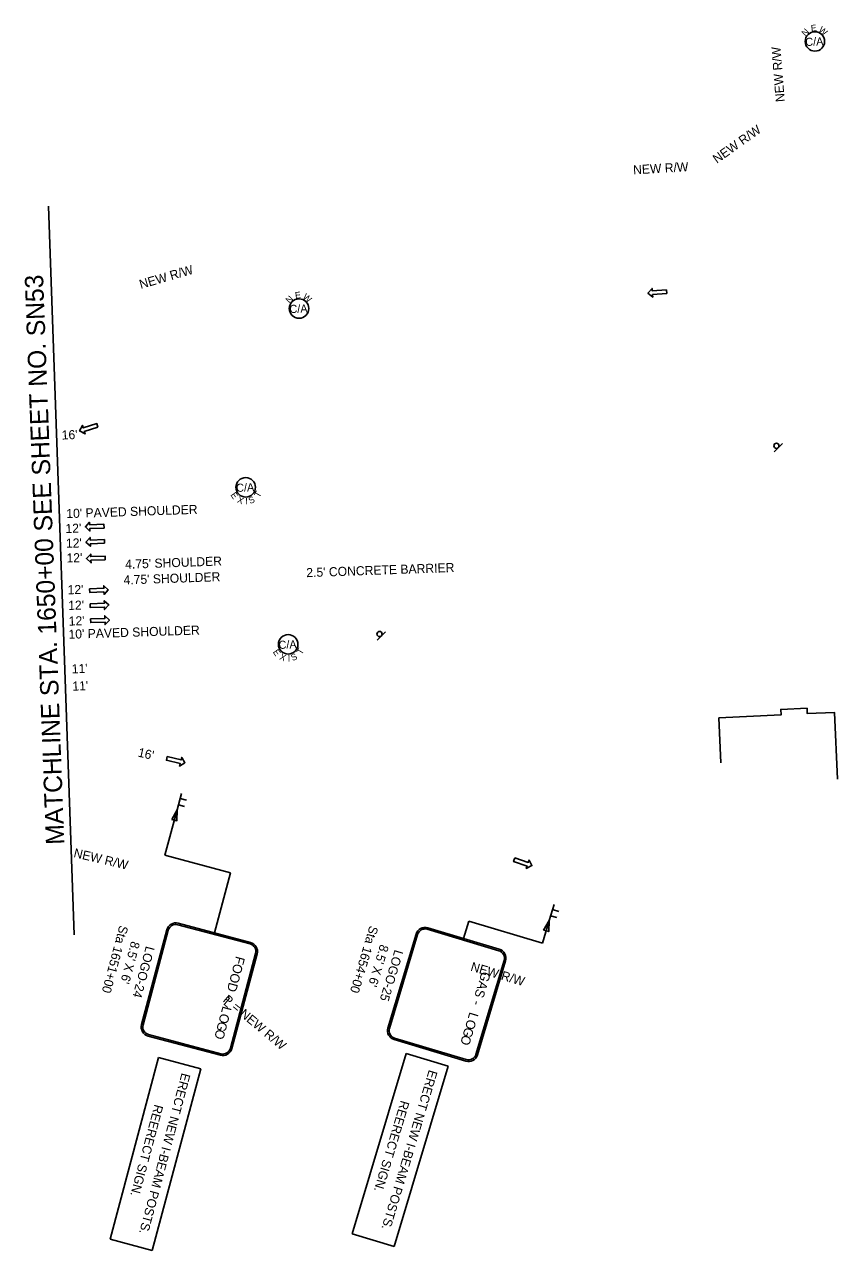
# Model space of a CAD drawing. Extents: x 1811940 to 1813538, y 1189643 to 1190703.
# Drawn here: x 1811940 to 1812567, y 1189643 to 1190588 of the extents above; entities that cross this region are included whole.
import ezdxf

# ---------------------------------------------------------------- set-up
doc = ezdxf.new("R2010")
doc.units = 0
for name, color, linetype in [('RD_EX_Bldg', 7, 'Continuous'), ('RD_PD_Final_LnLine', 7, 'Continuous'), ('RD_PD_Final_TX', 7, 'Continuous'), ('RD_PD_RW_TX', 7, 'Continuous'), ('RD_SHT_MatchLine', 7, 'Continuous'), ('RD_SHT_TX', 7, 'Continuous'), ('RD_Sketch10', 7, 'Continuous'), ('RD_Sketch8', 7, 'Continuous'), ('SN_P_Signs', 7, 'Continuous')]:
    doc.layers.add(name, color=color, linetype=linetype)

# ---------------------------------------------------------------- blocks, each defined once
blk = doc.blocks.new('SARRW2')
at = {"layer": 'RD_PD_Final_LnLine'}
blk.add_lwpolyline([(-12, 1.2), (-12, -1.2), (-2.83, -1.2), (-2.83, -2.83), (0, 0), (-2.83, 2.83), (-2.83, 1.2)], close=True, dxfattribs=at)

msp = doc.modelspace()

# ---------------------------------------------------------------- linework, layer by layer
at = {"layer": 'RD_EX_Bldg'}
for points in [[(1812566.77, 1190006.57), (1812564.48, 1190057.93), (1812543.53, 1190057), (1812543.35, 1190061.17), (1812523.1, 1190060.27), (1812523.29, 1190056.01), (1812475.3, 1190053.87)], [(1812475.3, 1190053.87), (1812476.85, 1190019.12)]]:
    msp.add_lwpolyline(points, dxfattribs=at)
at = {"layer": 'RD_SHT_MatchLine'}
msp.add_line((1811958.91, 1190448.21), (1811978.7, 1189886.47), dxfattribs=at)
at = {"layer": 'RD_Sketch10'}
for centre in [(1812549.38, 1190575.24), (1812151.93, 1190369.31)]:
    msp.add_circle(centre, 7.5, dxfattribs=at)
at = {"layer": 'RD_Sketch8'}
for centre in [(1812110.86, 1190231.48), (1812143.53, 1190110.42)]:
    msp.add_circle(centre, 7.5, dxfattribs=at)
at = {"layer": 'SN_P_Signs'}
for p, q in [((1812517.96, 1190258.86), (1812524.32, 1190265.22)), ((1812212.19, 1190113.74), (1812218.55, 1190120.1)), ((1812057.98, 1189982.84), (1812061.33, 1189995.44)), ((1812060.27, 1189991.46), (1812065.1, 1189990.18)), ((1812048.64, 1189947.82), (1812057.98, 1189982.84)), ((1812058.98, 1189986.61), (1812063.8, 1189985.33)), ((1812048.64, 1189947.82), (1812099.06, 1189934.38)), ((1812086.7, 1189888.01), (1812099.06, 1189934.38)), ((1812344.65, 1189897.43), (1812348.39, 1189909.92)), ((1812347.21, 1189905.98), (1812351.99, 1189904.55)), ((1812278.65, 1189883.63), (1812282.68, 1189897.1)), ((1812339.46, 1189880.1), (1812282.68, 1189897.1)), ((1812339.46, 1189880.1), (1812344.65, 1189897.43)), ((1812345.77, 1189901.17), (1812350.55, 1189899.74)), ((1812006.35, 1189651.78), (1812043.69, 1189791.91)), ((1812043.69, 1189791.91), (1812076.17, 1189783.25)), ((1812192.94, 1189655.95), (1812234.53, 1189794.88)), ((1812234.53, 1189794.88), (1812266.74, 1189785.24)), ((1812076.17, 1189783.25), (1812038.83, 1189643.12)), ((1812266.74, 1189785.24), (1812225.15, 1189646.31)), ((1812038.83, 1189643.12), (1812006.35, 1189651.78)), ((1812225.15, 1189646.31), (1812192.94, 1189655.95))]:
    msp.add_line(p, q, dxfattribs=at)
for points in [[(1812053.88, 1189975.44), (1812057.98, 1189982.84), (1812057.84, 1189974.38)], [(1812340.33, 1189890.16), (1812344.65, 1189897.43), (1812344.26, 1189888.98)]]:
    msp.add_lwpolyline(points, close=True, dxfattribs=at)
for points in [[(1812058.56, 1189894.27), (1812114.22, 1189879.43)], [(1812058.87, 1189895.43), (1812114.53, 1189880.59)], [(1812030.59, 1189817.27), (1812050.06, 1189890.32)], [(1812031.75, 1189816.96), (1812051.22, 1189890.01)], [(1812220.41, 1189814.63), (1812242.09, 1189887.06)], [(1812221.56, 1189814.29), (1812243.24, 1189886.71)], [(1812250.71, 1189890.74), (1812305.89, 1189874.22)], [(1812251.06, 1189891.89), (1812306.24, 1189875.37)], [(1812118.47, 1189872.09), (1812099, 1189799.04)], [(1812119.63, 1189871.78), (1812100.16, 1189798.73)], [(1812309.92, 1189866.75), (1812288.24, 1189794.33)], [(1812311.07, 1189866.41), (1812289.39, 1189793.98)], [(1812091.66, 1189794.79), (1812036, 1189809.62)], [(1812091.35, 1189793.63), (1812035.69, 1189808.46)], [(1812280.43, 1189789.15), (1812225.24, 1189805.67)], [(1812280.77, 1189790.3), (1812225.59, 1189806.82)]]:
    msp.add_lwpolyline(points, dxfattribs=at)
for centre in [(1812519.72, 1190263.48), (1812213.95, 1190118.37)]:
    msp.add_circle(centre, 2, dxfattribs=at)
for centre, radius, start, end in [((1812057.02, 1189888.47), 7.2, 75.0772, 165.0772), ((1812057.02, 1189888.47), 6, 75.0772, 165.0772), ((1812248.99, 1189884.99), 7.2, 73.33399, 163.33399), ((1812248.99, 1189884.99), 6, 73.33399, 163.33399), ((1812112.67, 1189873.64), 6, 345.0772, 75.0772), ((1812112.67, 1189873.64), 7.2, 345.0772, 75.0772), ((1812304.17, 1189868.47), 7.2, 343.33399, 73.33399), ((1812304.17, 1189868.47), 6, 343.33399, 73.33399), ((1812037.55, 1189815.42), 7.2, 165.0772, 255.0772), ((1812037.55, 1189815.42), 6, 165.0772, 255.0772), ((1812227.31, 1189812.57), 7.2, 163.33399, 253.33399), ((1812227.31, 1189812.57), 6, 163.33399, 253.33399), ((1812093.2, 1189800.58), 7.2, 255.0772, 345.0772), ((1812093.2, 1189800.58), 6, 255.0772, 345.0772), ((1812282.49, 1189796.05), 7.2, 253.33399, 343.33399), ((1812282.49, 1189796.05), 6, 253.33399, 343.33399)]:
    msp.add_arc(centre, radius, start, end, dxfattribs=at)

# ---------------------------------------------------------------- block references
at = {"layer": 'RD_PD_Final_LnLine'}
for p, xscale, yscale, rotation in [((1812420.77, 1190381.24), 1.2000000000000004, 1.2000000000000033, -175.8416533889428), ((1811982.8, 1190274.95), 1.2000000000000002, 1.2000000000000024, -162.8808875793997), ((1811987.29, 1190201), 1.1999999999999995, 1.2000000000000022, -177.9816202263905), ((1811987.7, 1190189.29), 1.1999999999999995, 1.2000000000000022, -177.9816202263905), ((1811988.15, 1190176.52), 1.1999999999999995, 1.2000000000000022, -177.9816202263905), ((1812004.99, 1190152.38), 1.1999999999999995, 1.2000000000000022, 2.018379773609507), ((1812005.4, 1190140.76), 1.1999999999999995, 1.2000000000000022, 2.018379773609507), ((1812005.81, 1190129.14), 1.1999999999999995, 1.2000000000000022, 2.018379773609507), ((1812064.05, 1190019.09), 1.1999999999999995, 1.2000000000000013, -13.543119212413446), ((1812331.33, 1189939.81), 1.2, 1.200000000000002, -18.31884334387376)]:
    msp.add_blockref('SARRW2', p, dxfattribs=dict(at, xscale=xscale, yscale=yscale, rotation=rotation))

# ---------------------------------------------------------------- texts
at = {"layer": 'RD_PD_Final_TX'}
for s, rotation, p in [("16'", 2.01838, (1811969.2, 1190268.28)), ("10' PAVED SHOULDER", 1.90447, (1811972.73, 1190207.7)), ("12'", 1.39156, (1811972.04, 1190196.24)), ("12'", 1.39156, (1811972.44, 1190184.86)), ("12'", 1.39156, (1811972.84, 1190173.49)), ("4.75' SHOULDER", 2.01838, (1812018.07, 1190168.61)), ("2.5' CONCRETE BARRIER", 2.02012, (1812157.65, 1190162.18)), ("4.75' SHOULDER", 2.01838, (1812016.82, 1190156.52)), ("12'", 1.39156, (1811973.71, 1190149)), ("12'", 1.39156, (1811974.13, 1190136.94)), ("12'", 1.39156, (1811974.56, 1190124.87)), ("10' PAVED SHOULDER", 1.90447, (1811974.41, 1190114.66)), ("11'", 2.01838, (1811976.94, 1190088.01)), ("11'", 2.01838, (1811977.41, 1190074.7)), ("16'", 347.20157, (1812027.35, 1190023.99)), ('P = NEW R/W', 319.97697, (1812092.75, 1189835.48)), ('L', 319.97697, (1812093.12, 1189833.21))]:
    msp.add_text(s, height=7, rotation=rotation, dxfattribs=at).set_placement(p)
at = {"layer": 'RD_PD_RW_TX'}
for rotation, p in [(94.47464, (1812526.2, 1190528.8)), (35.49974, (1812473.87, 1190480.86)), (3.19613, (1812409.49, 1190472.77)), (16.16642, (1812030.03, 1190384.39)), (346.6884, (1811977.82, 1189946.49)), (343.57346, (1812283.62, 1189858.97))]:
    msp.add_text('NEW R/W', height=7, rotation=rotation, dxfattribs=at).set_placement(p)
at = {"layer": 'RD_SHT_TX'}
msp.add_text('MATCHLINE STA. 1650+00 SEE SHEET NO. SN53', height=14.1726, rotation=92.14236, dxfattribs=at).set_placement((1811971.12, 1189956.18))
at = {"layer": 'RD_Sketch10'}
for s, height, rotation, p in [('N', 5, 46.88815, (1812542.13, 1190578.82)), ('E', 5, 6.35143, (1812546.55, 1190582.85)), ('W', 5, 321.321, (1812551.72, 1190583.29)), ('C/A', 6.25, 2.01838, (1812542.09, 1190571.71)), ('N', 5, 46.88815, (1812144.67, 1190372.9)), ('E', 5, 6.35143, (1812149.09, 1190376.92)), ('W', 5, 321.321, (1812154.27, 1190377.36)), ('C/A', 6.25, 2.01838, (1812144.63, 1190365.78))]:
    msp.add_text(s, height=height, rotation=rotation, dxfattribs=at).set_placement(p)
at = {"layer": 'RD_Sketch8'}
for s, height, rotation, p in [('C/A', 6.25, 2.01838, (1812103.57, 1190227.94)), ('E', 5, 305.22963, (1812098.84, 1190225.53)), ('T', 5, 60.20353, (1812121.35, 1190223.13)), ('X', 5, 337.659, (1812103.82, 1190220.04)), ('I', 5, 1.819, (1812110.67, 1190218.21)), ('S', 5, 23.81082, (1812114.31, 1190218.52)), ('C/A', 6.25, 2.01838, (1812136.24, 1190106.88)), ('E', 5, 305.22963, (1812131.51, 1190104.47)), ('X', 5, 337.659, (1812136.49, 1190098.98)), ('I', 5, 1.819, (1812143.34, 1190097.15)), ('S', 5, 23.81082, (1812146.98, 1190097.46)), ('T', 5, 60.20353, (1812154.02, 1190102.07))]:
    msp.add_text(s, height=height, rotation=rotation, dxfattribs=at).set_placement(p)
at = {"layer": 'SN_P_Signs'}
for s, height, rotation, p in [('Sta 1651+00', 7, 255.07728, (1812013.66, 1189894.22)), ('Sta 1654+00', 7, 253.33407, (1812206.4, 1189893.96)), ("8.5' X 6'", 7, 255.07728, (1812022.71, 1189881.95)), ('LOGO-24', 7, 255.07728, (1812034.02, 1189878.19)), ("8.5' X 6'", 7, 253.33407, (1812214.5, 1189879.51)), ('FOOD', 7.2, 255.0772, (1812103.43, 1189870.41)), ('LOGO-25', 7, 253.33407, (1812225.69, 1189875.42)), ('GAS', 7.2, 253.33399, (1812292.78, 1189858.65)), ('-', 7.2, 255.0772, (1812095.58, 1189840.94)), ('-', 7.2, 255.0772, (1812095.58, 1189840.94)), ('L', 7.2, 255.0772, (1812093.16, 1189831.88)), ('L', 7.2, 255.0772, (1812093.16, 1189831.88)), ('-', 7.2, 253.33399, (1812286.09, 1189836.31)), ('G', 7.2, 255.0772, (1812090.03, 1189820.14)), ('G', 7.2, 255.0772, (1812090.03, 1189820.14)), ('O', 7.2, 255.0772, (1812091.68, 1189826.34)), ('O', 7.2, 255.0772, (1812091.68, 1189826.34)), ('O', 7.2, 253.33399, (1812281.75, 1189821.83)), ('L', 7.2, 253.33399, (1812283.4, 1189827.33)), ('O', 7.2, 255.0772, (1812088.44, 1189814.16)), ('O', 7.2, 255.0772, (1812088.44, 1189814.16)), ('G', 7.2, 253.33399, (1812279.92, 1189815.69)), ('O', 7.2, 253.33399, (1812278.14, 1189809.76)), ('ERECT NEW I-BEAM POSTS.', 6.9998, 253.33407, (1812252.06, 1189782.8)), ('ERECT NEW I-BEAM POSTS.', 6.9998, 255.07728, (1812061.58, 1189780.37)), ('REERECT SIGN.', 6.9998, 255.07728, (1812040.63, 1189756.14)), ('REERECT SIGN.', 6.9998, 253.33407, (1812230.39, 1189759.23))]:
    msp.add_text(s, height=height, rotation=rotation, dxfattribs=at).set_placement(p)

doc.saveas('drawing.dxf')
